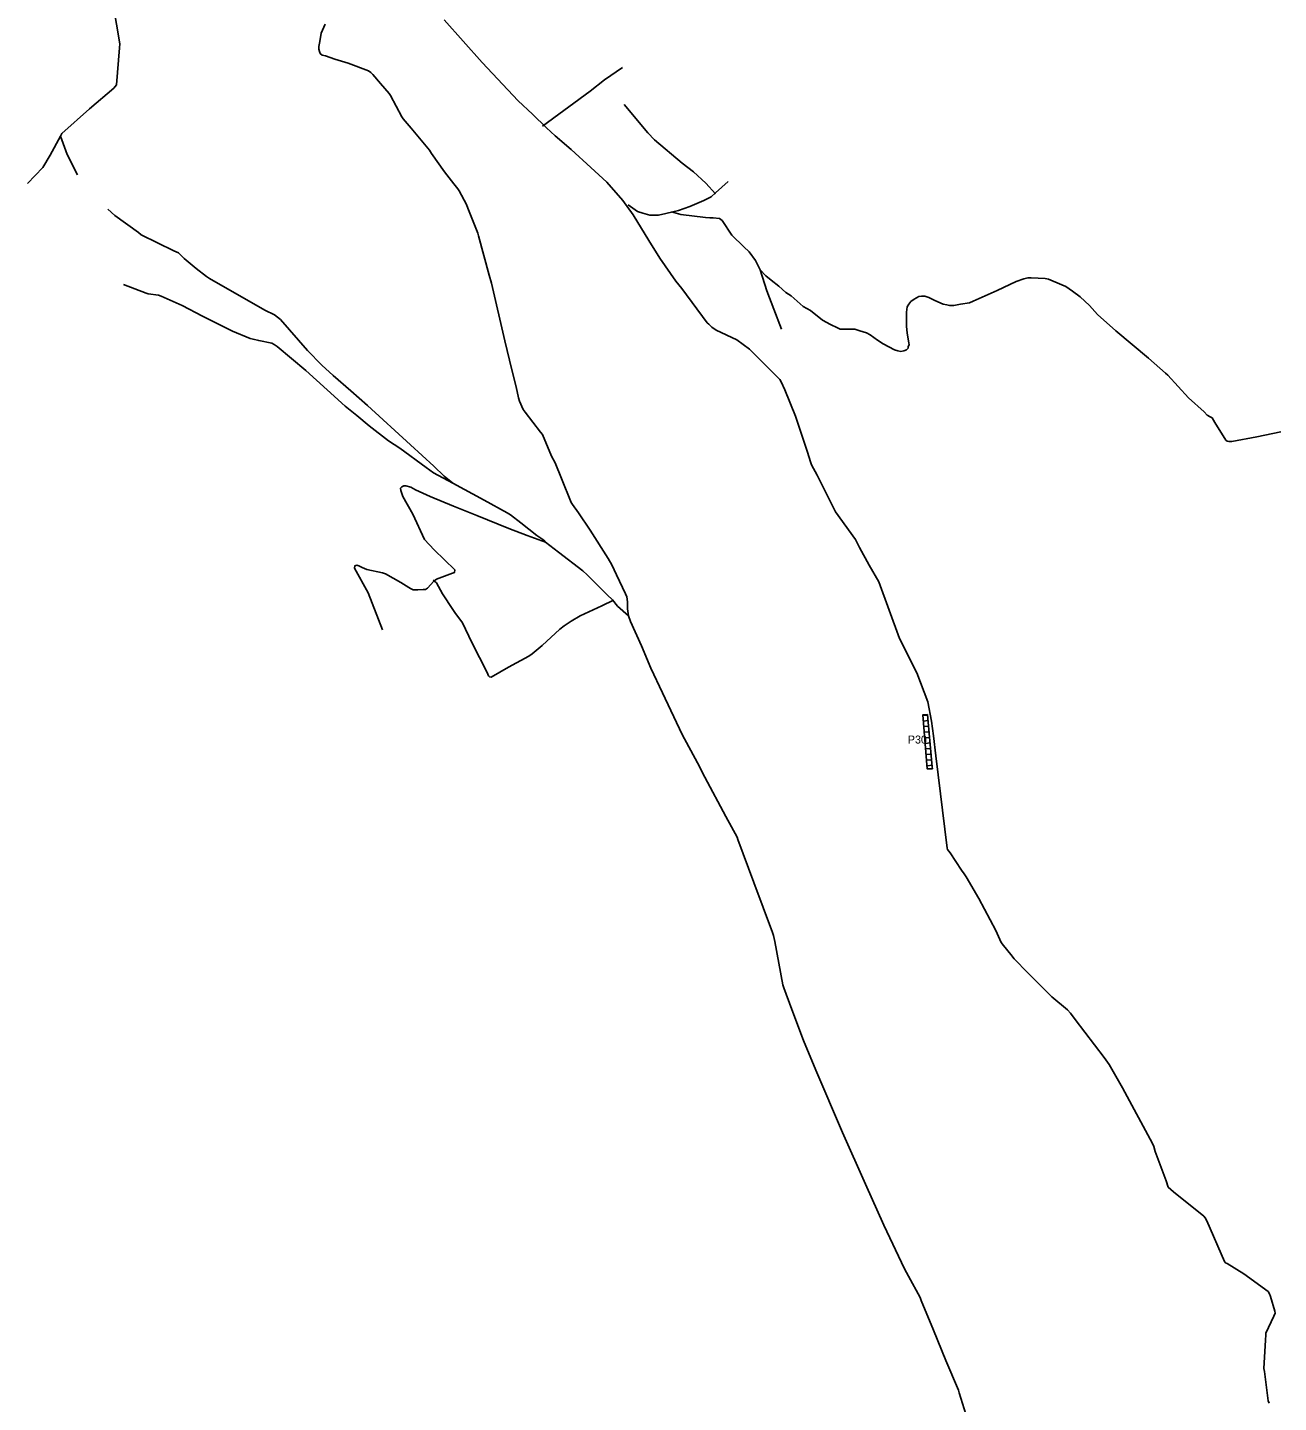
# Model space of a CAD drawing. Extents: x -439169 to -431590, y -1130011 to -1121081.
# Drawn here: x -437375 to -435812, y -1127374 to -1125656 of the extents above; entities that cross this region are included whole.
import ezdxf

# ---------------------------------------------------------------- set-up
doc = ezdxf.new("R2010")
doc.units = 0
for name, color, linetype in [('11811012_místní  komunikace_Stav', 7, 'Continuous'), ('11900012_účelová komunikace_Stav', 7, 'Continuous'), ('12080021_parkoviště mimo prostor komunikace_Návrh', 7, 'Continuous'), ('12080023_parkoviště mimo prostor komunikace_Návrh', 7, 'Continuous')]:
    doc.layers.add(name, color=color, linetype=linetype)

msp = doc.modelspace()

# ---------------------------------------------------------------- linework, layer by layer
at = {"layer": '11811012_místní  komunikace_Stav'}
for points in [[(-436854.6, -1125646.1), (-436806.8, -1125699.7), (-436761.8, -1125747.6), (-436744.2, -1125764.3), (-436726.8, -1125781.2), (-436715.6, -1125791.3), (-436695.6, -1125808.4), (-436671.4, -1125830.6), (-436651, -1125849.1), (-436631, -1125872.1), (-436618.4, -1125889.8), (-436598.8, -1125922.1), (-436585.1, -1125944), (-436565, -1125972.8), (-436557.4, -1125982.2), (-436525.8, -1126024.7), (-436523.8, -1126026.6), (-436519.8, -1126030.3), (-436514.6, -1126034), (-436488.8, -1126046.3), (-436480.7, -1126052), (-436472.9, -1126057.9), (-436434.9, -1126095.9), (-436433.3, -1126098.5), (-436428.9, -1126108.5), (-436415.4, -1126141.5), (-436400.5, -1126186.5), (-436396.7, -1126198.7), (-436395.6, -1126202.5), (-436388.4, -1126215.3), (-436365.3, -1126260.9), (-436340.6, -1126295.8), (-436335.4, -1126305.7), (-436323.5, -1126327.5), (-436311.3, -1126348.6), (-436285.6, -1126419.4), (-436263.6, -1126462.1), (-436250, -1126498.4)], [(-436515.4, -1125863.6), (-436527.5, -1125850.2), (-436543, -1125836.1), (-436557, -1125825.4), (-436591.6, -1125796.1), (-436600.1, -1125787.6), (-436629.4, -1125752)], [(-436624.5, -1125877.3), (-436613, -1125885.7), (-436606.4, -1125887.8), (-436597.5, -1125890.3), (-436586.8, -1125890.3), (-436577.6, -1125888.3), (-436561.8, -1125884.6), (-436547.5, -1125879.7), (-436529.9, -1125871.9), (-436520.7, -1125867.5), (-436515.2, -1125862.4), (-436499.7, -1125848.4)], [(-436570.5, -1125886.3), (-436558.6, -1125889.7), (-436527.7, -1125893.4), (-436522.5, -1125893.7), (-436518.4, -1125893.8), (-436510.6, -1125894.4), (-436507, -1125897.2), (-436495, -1125915.5), (-436480.2, -1125929.8), (-436473.5, -1125936.3), (-436465.5, -1125947), (-436459.6, -1125958.7), (-436452.6, -1125966), (-436445.9, -1125971.6), (-436436.1, -1125978.9)], [(-436459.6, -1125958.7), (-436451.1, -1125984.8), (-436442.6, -1126007.9), (-436433.1, -1126032.6)], [(-436250, -1126498.4), (-436245.3, -1126522.8), (-436242.9, -1126541), (-436239.9, -1126566.1)], [(-436239.9, -1126566.1), (-436226, -1126681.2), (-436225.3, -1126682.8), (-436222.2, -1126687.1), (-436207.8, -1126708.9), (-436204.5, -1126713.4), (-436202, -1126717.3), (-436186.2, -1126744.4), (-436165.2, -1126784.2), (-436158.3, -1126799.3), (-436155.7, -1126802.8), (-436146.3, -1126814.4), (-436142.1, -1126819.4), (-436125.3, -1126836.9), (-436094.9, -1126867.1), (-436075.6, -1126883.4), (-436071.9, -1126887.5), (-436065.9, -1126895.6), (-436029.8, -1126942.8), (-436023.4, -1126951.8), (-436006.6, -1126980.7), (-435969.2, -1127050.4), (-435967.8, -1127054), (-435966.1, -1127060.2), (-435952.4, -1127096.8), (-435949.8, -1127104.8), (-435943.2, -1127110.8), (-435905.1, -1127141.2), (-435903.3, -1127143.1), (-435901.6, -1127146.9), (-435879.2, -1127197.9), (-435878.1, -1127199.4), (-435876.2, -1127200.3), (-435855, -1127213.2), (-435824.9, -1127235.3), (-435823.2, -1127238), (-435821.8, -1127241.7), (-435816.4, -1127260), (-435816, -1127262.2), (-435817.5, -1127266), (-435827.8, -1127287.2), (-435827.6, -1127289.3), (-435828.2, -1127295.9), (-435830, -1127331.6), (-435829.5, -1127335.1), (-435824.9, -1127372.1), (-435823.5, -1127374.9)]]:
    msp.add_lwpolyline(points, dxfattribs=at)
at = {"layer": '11900012_účelová komunikace_Stav'}
for points in [[(-437268.2, -1125627.2), (-437259.6, -1125676.1), (-437260, -1125681.1), (-437264, -1125727.6), (-437267.3, -1125731.5), (-437297.7, -1125757.5), (-437332.1, -1125788.3), (-437333.8, -1125791.8), (-437346.8, -1125815.3), (-437356, -1125830.7), (-437375.2, -1125850.6)], [(-437003, -1125651.7), (-437008.1, -1125662.9), (-437009.1, -1125668.4), (-437010.4, -1125675.6), (-437010.9, -1125679.6), (-437010.9, -1125682.8), (-437010.4, -1125685.7), (-437009.6, -1125688.3), (-437007, -1125690.3), (-437002.8, -1125691.3), (-436991.2, -1125695.3), (-436974.6, -1125700.5), (-436949.2, -1125710.2), (-436946.1, -1125711.9), (-436943.7, -1125714.5), (-436934.1, -1125725.7), (-436923.4, -1125738.4), (-436921.6, -1125741), (-436907.4, -1125767.3), (-436905.9, -1125769.9), (-436895.7, -1125781.8), (-436873, -1125809.3), (-436870.2, -1125813.5), (-436854.2, -1125836.2), (-436842.2, -1125851.1), (-436837.3, -1125857.3), (-436835.6, -1125860.1), (-436826.6, -1125877.2), (-436824.7, -1125881.7), (-436812.4, -1125912.7), (-436811.5, -1125916.2), (-436798.2, -1125965.5), (-436795.5, -1125975.3), (-436778.7, -1126047.4), (-436769.9, -1126083.8), (-436764.4, -1126105), (-436761.4, -1126118.8), (-436760.3, -1126122.9), (-436755.7, -1126133.1), (-436753.2, -1126136.4), (-436734, -1126161.5), (-436731.8, -1126164.4), (-436720.2, -1126191.4), (-436715.9, -1126200), (-436708, -1126219.5), (-436695.9, -1126249.2), (-436694, -1126252.1), (-436686.5, -1126262.3), (-436672.1, -1126284.1), (-436649.6, -1126319.3), (-436645, -1126327.3), (-436639.3, -1126339.8), (-436627.7, -1126363.5), (-436626.1, -1126367.4), (-436625.5, -1126373.5), (-436625.3, -1126382.3), (-436624.2, -1126391.2)], [(-436731.8, -1125779.1), (-436672, -1125735.4), (-436654.2, -1125721.4), (-436631.5, -1125705.8)], [(-437333.8, -1125791.8), (-437325.5, -1125814.4), (-437312.6, -1125839.8)], [(-436624.2, -1126391.2), (-436637.7, -1126378.8), (-436644.2, -1126371), (-436650.9, -1126364.7), (-436675.7, -1126339.8), (-436681.1, -1126334.9), (-436711.4, -1126311.6), (-436727.7, -1126299), (-436730.1, -1126296.6), (-436738.7, -1126290.5), (-436758.8, -1126275), (-436771.4, -1126264.9), (-436775.8, -1126262.3), (-436804.5, -1126246.5), (-436843.5, -1126225.2), (-436854.4, -1126216.3), (-436867.5, -1126203.8), (-436896.6, -1126177.4), (-436950.4, -1126128.1), (-436971.2, -1126109.8), (-436993.2, -1126090.7), (-437007.2, -1126077.6), (-437025.1, -1126059.6), (-437059.1, -1126020.9), (-437066.5, -1126014.7), (-437078.5, -1126009.1), (-437147.9, -1125969.4), (-437151.6, -1125967), (-437164.5, -1125956.8), (-437179.2, -1125944.6), (-437186.6, -1125937.4), (-437192.1, -1125935.1), (-437233, -1125914.9), (-437236.3, -1125912.1), (-437266.1, -1125890.8), (-437274.9, -1125883)], [(-436436.1, -1125978.9), (-436427.5, -1125986.9), (-436421, -1125991.3), (-436405.9, -1126004.6), (-436396.7, -1126009.4), (-436381.6, -1126021.4), (-436371.7, -1126026.9), (-436362.9, -1126031.1), (-436359.7, -1126032.9), (-436354.6, -1126032.7), (-436341.3, -1126032.9), (-436335.2, -1126034.8), (-436326.8, -1126037.4), (-436322.1, -1126039.9), (-436312.9, -1126046.4), (-436306, -1126051), (-436291.6, -1126058.5), (-436287.7, -1126060), (-436283.7, -1126060.6), (-436280, -1126060), (-436276.7, -1126058.5), (-436274.8, -1126056.7), (-436274.5, -1126054.5), (-436273.2, -1126052.3), (-436273.7, -1126049.7), (-436275.2, -1126042.7), (-436275.9, -1126037.3), (-436276.7, -1126029.4), (-436276.7, -1126020), (-436276.9, -1126011.7), (-436275.8, -1126005.1), (-436273.6, -1126001.4), (-436271.3, -1125998.3), (-436267.1, -1125995.5), (-436261.4, -1125992), (-436257.9, -1125991.5), (-436253.8, -1125991.5), (-436248.7, -1125993.1), (-436241.5, -1125996.8), (-436230.7, -1126001.4), (-436226.2, -1126002.5), (-436222.9, -1126003.4), (-436217.6, -1126003.2), (-436209.3, -1126001.6), (-436198.2, -1126000.1), (-436193.4, -1125997.9), (-436163.3, -1125984.5), (-436139.7, -1125973.2), (-436129.9, -1125969.9), (-436124.9, -1125968.5), (-436120.9, -1125968.5), (-436103.4, -1125969.6), (-436099.4, -1125970.3), (-436082.4, -1125977.5), (-436077.5, -1125979.7), (-436069.2, -1125985.4), (-436059.6, -1125992.2), (-436048, -1126003.1), (-436038.2, -1126014.5), (-436015.2, -1126035), (-435974.5, -1126069), (-435953, -1126087.8), (-435950.3, -1126090.2), (-435924.3, -1126118.8), (-435904.6, -1126136.1), (-435900.9, -1126140.3), (-435897.2, -1126142.5), (-435894.6, -1126143.8), (-435891.5, -1126149.5), (-435877.7, -1126171.4), (-435875.9, -1126172.7), (-435873.6, -1126173.3), (-435870.3, -1126173.3), (-435838.8, -1126167.2), (-435808.8, -1126161.3)], [(-437255, -1125977.1), (-437227, -1125988), (-437224.2, -1125988.7), (-437211.5, -1125990.4), (-437208.2, -1125991.5), (-437181.8, -1126003.4), (-437156.6, -1126016.7), (-437119.1, -1126035.1), (-437097.1, -1126044.5), (-437093.3, -1126045.4), (-437086.1, -1126047.1), (-437069.9, -1126050.4), (-437067, -1126052), (-437063.3, -1126054.6), (-437027.2, -1126084.3), (-437000.7, -1126108.8), (-436978.2, -1126129.2), (-436963.8, -1126140.6), (-436948.1, -1126153.6), (-436924.2, -1126172.3), (-436910, -1126181.5), (-436876.9, -1126205.6), (-436867.9, -1126212.3), (-436843.5, -1126225.2)], [(-436727.7, -1126299), (-436750.9, -1126290.5), (-436773.8, -1126281.8), (-436813.6, -1126265.6), (-436842.9, -1126253.8), (-436871.8, -1126241.9), (-436890.2, -1126233.4), (-436896.3, -1126230.3), (-436902.2, -1126228.6), (-436904.9, -1126228.6), (-436907.3, -1126229.7), (-436909, -1126231.6), (-436908.6, -1126234.5), (-436906.1, -1126241.7), (-436893.8, -1126263.8), (-436879.2, -1126295.8), (-436866.8, -1126308.5), (-436841.1, -1126333.6), (-436841.5, -1126336.8), (-436844.1, -1126337.6), (-436864.1, -1126345.1), (-436867.4, -1126347.5), (-436875.5, -1126356.6), (-436877.7, -1126358.1), (-436880.9, -1126357.9), (-436887.3, -1126358.6), (-436893.2, -1126358.6), (-436896.5, -1126357), (-436898.8, -1126355.7), (-436908.8, -1126349.2), (-436927.8, -1126338.4), (-436931.4, -1126337.1), (-436951.2, -1126333), (-436957.1, -1126330.6), (-436961, -1126328.7), (-436963.6, -1126327.9), (-436966.1, -1126328.5), (-436966.6, -1126331.5), (-436949.4, -1126362.3), (-436931.7, -1126408.7)], [(-436868.3, -1126346.5), (-436864.1, -1126349.8), (-436856.4, -1126363.4), (-436843.7, -1126382.9), (-436841.3, -1126386.9), (-436831.7, -1126399.7), (-436820.1, -1126424.2), (-436800.8, -1126461.8), (-436799.2, -1126466.1), (-436797.8, -1126467.1), (-436795.6, -1126467.6), (-436774.1, -1126455), (-436748.8, -1126441.6), (-436744.7, -1126438.5), (-436732, -1126428), (-436709.9, -1126407.7), (-436704.7, -1126403.3), (-436695.7, -1126397.7), (-436684.6, -1126391.1), (-436657.3, -1126378.6), (-436642.8, -1126371.5)], [(-436624.2, -1126391.2), (-436621.8, -1126398), (-436607.8, -1126428.7), (-436596.2, -1126456.2), (-436581.7, -1126487.3), (-436557.2, -1126539.2), (-436538, -1126574.6), (-436528.7, -1126592.5), (-436502.3, -1126641.9), (-436488.5, -1126667.7), (-436487.6, -1126670.4), (-436467.7, -1126724.3), (-436444, -1126786.9), (-436443.1, -1126790.4), (-436441.4, -1126798.1), (-436431.3, -1126852.2), (-436430.2, -1126855.9), (-436420, -1126882.8), (-436405.3, -1126921.8), (-436390.2, -1126958.8), (-436356.9, -1127036.5), (-436328, -1127101.3), (-436304.9, -1127152.3), (-436279.4, -1127206.8), (-436274.2, -1127216.2), (-436259.8, -1127242.6), (-436258.2, -1127246.5), (-436242.9, -1127283.4), (-436227.4, -1127321.6), (-436211.8, -1127358.6), (-436210.9, -1127362.1), (-436194.1, -1127415.3)]]:
    msp.add_lwpolyline(points, dxfattribs=at)
at = {"layer": '12080021_parkoviště mimo prostor komunikace_Návrh'}
for p, q in [((-436250.5, -1126515.1), (-436256.1, -1126515.6)), ((-436249.9, -1126522), (-436255.5, -1126522.5)), ((-436249.3, -1126529), (-436255, -1126529.5)), ((-436248.6, -1126536), (-436254.4, -1126536.5)), ((-436248, -1126542.9), (-436253.9, -1126543.5)), ((-436247.3, -1126549.9), (-436253.3, -1126550.4)), ((-436246.7, -1126556.9), (-436252.7, -1126557.4)), ((-436246, -1126563.9), (-436252.2, -1126564.4)), ((-436245.3, -1126570.8), (-436251.6, -1126571.4)), ((-436244.7, -1126577.8), (-436251.1, -1126578.4))]:
    msp.add_line(p, q, dxfattribs=at)
msp.add_lwpolyline([(-436250.5, -1126514.2), (-436256.2, -1126514.6), (-436250.7, -1126582.3), (-436244.4, -1126582.1), (-436244.5, -1126579.7), (-436247.2, -1126551.8), (-436249.7, -1126523.9)], close=True, dxfattribs=at)

# ---------------------------------------------------------------- texts
at = {"layer": '12080023_parkoviště mimo prostor komunikace_Návrh'}
msp.add_text('P30', height=10, dxfattribs=at).set_placement((-436275, -1126550.6))

doc.saveas('drawing.dxf')
